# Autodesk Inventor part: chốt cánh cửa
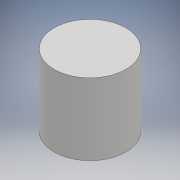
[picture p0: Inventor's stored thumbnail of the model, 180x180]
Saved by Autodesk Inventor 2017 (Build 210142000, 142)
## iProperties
Created: 2022-04
Part Number: chốt cánh cửa
Material: Generic
Document SubType Name: Sheet Metal
Designer: phat
Density: 1 g/cm^3
Sheet Metal Rule: Default_mm
Appearance: Default
Author: phat
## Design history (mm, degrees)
sketch "Sketch1"
  geometry: C1 r 2.5 at (0, 0); 1 further point
  constraints: 1 centre point, 1 coincident
  dimensions: "d0" = 5 diameter of C1
extrude "Extrusion1" new body sketch "Sketch1" distance "d1" = 5; taper "d2" = 0 deg
body "Solid1"
other parameters: "Thickness" = 0.5, "BendRadius" = 0.5 (= Thickness), "BendReliefWidth" = 0.5 (= Thickness), "BendReliefDepth" = 0.25 (= 0.5 x Thickness), "CornerReliefSize" = 2 (= 4 x Thickness), "SeamGap" = 0.01, "MinimumRemnant" = 1 (= 2 x Thickness), "TransitionRadius" = 0.5 (= BendRadius), "JacobiRadiusSize" = 0.5 (= BendRadius), "GapSize" = 0.5 (= Thickness)
